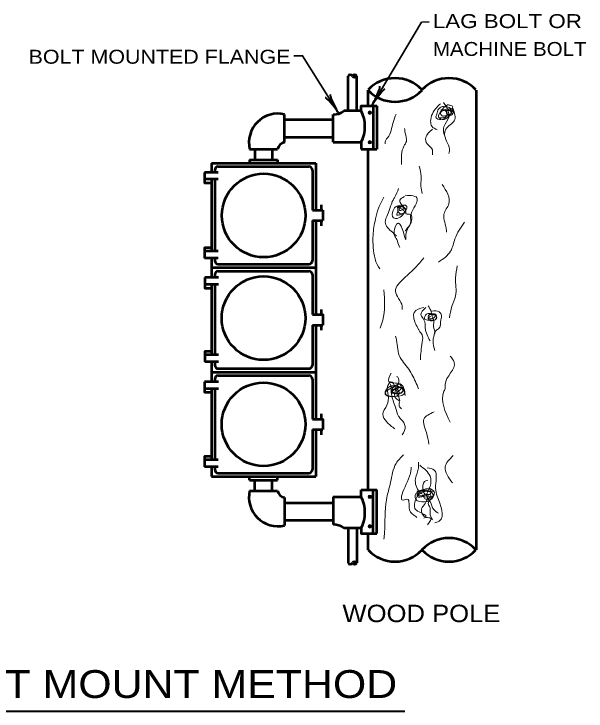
# Model space of a CAD drawing. Extents: x -286 to 394, y -156 to 284.
# Drawn here: x -179.2 to -97.1, y -8 to 92.1 of the extents above; entities that cross this region are included whole.
import ezdxf
from ezdxf.enums import TextEntityAlignment as Align

# ---------------------------------------------------------------- set-up
doc = ezdxf.new("R2010")
doc.units = 0
doc.header["$LTSCALE"] = 0.8
doc.layers.add('1', color=7, linetype='Continuous', lineweight=53)

msp = doc.modelspace()

# ---------------------------------------------------------------- hatches: boundary and pattern name
at = {"layer": '1'}
for points in [[(-127.854, 77.9357, 1), (-128.354, 77.9357, 1)], [(-127.854, 73.6894, 1), (-128.354, 73.6894, 1)], [(-127.854, 22.7843, 1), (-128.354, 22.7843, 1)], [(-127.854, 18.5379, 1), (-128.354, 18.5379, 1)]]:
    msp.add_hatch(color=256, dxfattribs=at).paths.add_polyline_path(points)

# ---------------------------------------------------------------- linework, layer by layer
at = {"layer": '1', "lineweight": 35}
for p, q in [((-127.7725, 79.0342), (-120.6713, 90.9517)), ((-120.6713, 90.9517), (-119.5732, 90.9644))]:
    msp.add_line(p, q, dxfattribs=at)
at = {"layer": '1'}
for p, q in [((-131.2278, 78.1877), (-131.2278, 83.1877)), ((-129.9778, 78.1877), (-129.9778, 83.1877)), ((-128.3528, 78.9377), (-128.3528, 81.1877)), ((-112.8528, 81.1877), (-112.8528, 15.1619)), ((-129.3528, 78.1877), (-131.8528, 78.1877)), ((-127.6028, 78.9377), (-127.6028, 72.6877)), ((-127.1028, 78.9377), (-127.1028, 72.6877)), ((-140.3528, 73.6877), (-140.3528, 77.6877)), ((-133.3528, 73.6877), (-133.3528, 77.6877)), ((-140.3528, 76.9377), (-133.3528, 76.9377)), ((-140.3528, 74.4377), (-133.3528, 74.4377)), ((-145.3528, 72.6877), (-141.3528, 72.6877)), ((-144.6028, 72.6877), (-144.6028, 71.1877)), ((-142.1028, 72.6877), (-142.1028, 71.1877)), ((-129.3528, 72.6877), (-127.1028, 72.6877)), ((-128.3528, 23.7859), (-128.3528, 72.6877)), ((-145.3528, 71.1877), (-141.3528, 71.1877)), ((-145.3528, 71.1877), (-145.3528, 70.6877)), ((-141.3528, 71.1877), (-141.3528, 70.6877)), ((-150.8528, 70.6877), (-135.8528, 70.6877)), ((-150.8528, 70.6877), (-150.8528, 69.3678)), ((-149.8528, 70.1877), (-136.8528, 70.1877)), ((-135.8528, 70.6877), (-135.8528, 63.9378)), ((-149.8528, 69.3678), (-151.8528, 69.3678)), ((-150.3528, 69.6877), (-150.3528, 69.3678)), ((-136.3528, 69.6877), (-136.3528, 63.9378)), ((-149.8528, 68.3678), (-151.8528, 68.3678)), ((-150.8528, 68.3678), (-150.8528, 58.0468)), ((-150.3528, 68.3678), (-150.3528, 58.0468)), ((-135.1028, 64.6877), (-135.1028, 63.9378)), ((-136.3528, 63.9378), (-134.8528, 63.9378)), ((-134.8528, 63.9378), (-134.8528, 62.4378)), ((-136.3528, 62.4378), (-136.3528, 56.6878)), ((-136.3528, 62.4378), (-134.8528, 62.4378)), ((-135.8528, 62.4378), (-135.8528, 48.9378)), ((-135.1028, 62.4378), (-135.1028, 61.6878)), ((-149.8528, 58.0468), (-151.8528, 58.0468)), ((-149.8528, 57.0468), (-151.8528, 57.0468)), ((-150.8528, 57.0468), (-150.8528, 54.2587)), ((-150.3528, 57.0468), (-150.3528, 56.6878)), ((-149.8528, 56.1878), (-136.8528, 56.1878)), ((-150.8528, 55.6878), (-135.8528, 55.6878)), ((-149.8528, 55.1878), (-136.8528, 55.1878)), ((-149.8113, 54.2587), (-151.8113, 54.2587)), ((-150.3528, 54.6878), (-150.3528, 54.2587)), ((-136.3528, 54.6878), (-136.3528, 48.9378)), ((-149.8113, 53.2587), (-151.8113, 53.2587)), ((-150.8528, 53.2587), (-150.8528, 43.1597)), ((-150.3528, 53.2587), (-150.3528, 43.1597)), ((-135.1028, 49.6878), (-135.1028, 48.9378)), ((-136.3528, 47.4378), (-134.8528, 47.4378)), ((-136.3528, 47.4378), (-136.3528, 41.6878)), ((-135.8528, 47.4378), (-135.8528, 33.9378)), ((-135.1028, 47.4378), (-135.1028, 46.6878)), ((-149.8113, 43.1597), (-151.8113, 43.1597)), ((-149.8113, 42.1597), (-151.8113, 42.1597)), ((-150.8528, 42.1597), (-150.8528, 39.2854)), ((-150.3528, 42.1597), (-150.3528, 41.6878)), ((-149.8528, 41.1878), (-136.8528, 41.1878)), ((-150.8528, 40.6878), (-135.8528, 40.6878)), ((-149.8528, 40.1878), (-136.8528, 40.1878)), ((-149.8279, 39.2854), (-151.8279, 39.2854)), ((-150.3528, 39.6878), (-150.3528, 39.2854)), ((-136.3528, 39.6878), (-136.3528, 33.9378)), ((-149.8279, 38.2854), (-151.8279, 38.2854)), ((-150.8528, 38.2854), (-150.8528, 28.0879)), ((-150.3528, 38.2854), (-150.3528, 28.0879)), ((-135.1028, 34.6878), (-135.1028, 33.9378)), ((-136.3528, 32.4378), (-134.8528, 32.4378)), ((-136.3528, 32.4378), (-136.3528, 26.6877)), ((-135.8528, 32.4378), (-135.8528, 25.6877)), ((-135.1028, 32.4378), (-135.1028, 31.6877)), ((-149.8543, 28.0879), (-151.8543, 28.0879)), ((-149.8543, 27.0879), (-151.8543, 27.0879)), ((-150.8528, 27.0879), (-150.8528, 25.6877)), ((-150.3528, 27.0879), (-150.3528, 26.6877)), ((-149.8528, 26.1877), (-136.8528, 26.1877)), ((-150.8528, 25.6877), (-135.8528, 25.6877)), ((-145.3528, 25.1619), (-145.3528, 25.6619)), ((-145.3528, 25.1619), (-141.3528, 25.1619)), ((-144.6028, 23.6619), (-144.6028, 25.1619)), ((-142.1028, 23.6619), (-142.1028, 25.1619)), ((-141.3528, 25.1619), (-141.3528, 25.6619)), ((-145.3528, 23.6619), (-141.3528, 23.6619)), ((-129.3528, 22.7859), (-129.3528, 23.7859)), ((-129.3528, 23.7859), (-127.1028, 23.7859)), ((-127.6028, 17.5359), (-127.6028, 23.7859)), ((-127.1028, 17.5359), (-127.1028, 23.7859)), ((-140.3528, 22.6619), (-140.3528, 18.6619)), ((-133.3528, 22.7859), (-129.3528, 22.7859)), ((-133.3528, 22.7859), (-133.3528, 18.7859)), ((-140.3528, 21.9119), (-133.3528, 21.9119)), ((-140.3528, 19.4119), (-133.3528, 19.4119)), ((-129.3528, 18.2859), (-131.8528, 18.2859)), ((-131.2278, 18.2859), (-131.2278, 13.2859)), ((-129.9778, 18.2859), (-129.9778, 13.2859)), ((-128.3528, 15.1619), (-128.3528, 17.5359))]:
    msp.add_line(p, q, dxfattribs=at)
at = {"layer": '1', "lineweight": 40}
msp.add_line((-195.529, -7.9817), (-123.0741, -7.9817), dxfattribs=at)
at = {"layer": '1', "lineweight": 35}
msp.add_lwpolyline([(-132.6176, 77.8785), (-137.7608, 86.1178), (-138.9907, 86.1178)], dxfattribs=at)
at = {"layer": '1'}
for points in [[(-129.3528, 78.1877), (-129.3528, 78.9377), (-127.1028, 78.9377)], [(-133.3528, 73.6877), (-129.3528, 73.6877), (-129.3528, 72.6877)], [(-151.8528, 69.3678), (-151.8528, 67.8678), (-150.8528, 67.8678)], [(-150.8528, 58.5468), (-151.8528, 58.5468), (-151.8528, 57.0468)], [(-151.8113, 54.2587), (-151.8113, 52.7587), (-150.8528, 52.7587)], [(-136.3528, 48.9378), (-134.8528, 48.9378), (-134.8528, 47.4378)], [(-150.8113, 43.6597), (-151.8113, 43.6597), (-151.8113, 42.1597)], [(-151.8279, 39.2854), (-151.8279, 37.7854), (-150.8279, 37.7854)], [(-136.3528, 33.9378), (-134.8528, 33.9378), (-134.8528, 32.4378)], [(-150.8543, 28.5879), (-151.8543, 28.5879), (-151.8543, 27.0879)], [(-129.3528, 18.2859), (-129.3528, 17.5359), (-127.1028, 17.5359)]]:
    msp.add_lwpolyline(points, dxfattribs=at)
at = {"layer": '1', "lineweight": 13}
for centre in [(-128.104, 77.9357), (-128.104, 73.6894), (-128.104, 22.7843), (-128.104, 18.5379)]:
    msp.add_circle(centre, 0.25, dxfattribs=at)
at = {"layer": '1'}
for centre in [(-143.3466, 63.1818), (-143.358, 48.4382), (-143.3584, 33.1901)]:
    msp.add_circle(centre, 6, dxfattribs=at)
for centre, radius, start, end in [((-130.9153, 82.9868), 0.3715, 32.74583, 147.25417), ((-130.2903, 82.9868), 0.3715, 32.74583, 147.25417), ((-130.2903, 83.3876), 0.3715, 212.74583, 327.25417), ((-124.4778, 77.5927), 5.2962, 42.97503, 137.02497), ((-116.7397, 77.5927), 5.2962, 42.97503, 137.02497), ((-124.4778, 84.7981), 5.2962, 222.97503, 317.02497), ((-133.2241, 79.8017), 2.1178, 266.51631, 310.35359), ((-133.5969, 75.9377), 4.8036, 332.0697, 27.9303), ((-141.2973, 73.6322), 4.164, 76.89015, 193.10985), ((-140.0693, 72.4042), 1.3145, 102.45679, 167.54321), ((-149.8528, 69.6877), 0.5, 90, 180), ((-136.8528, 69.6877), 0.5, 0, 90), ((-149.8528, 56.6878), 0.5, 180, 270), ((-136.8528, 56.6878), 0.5, 270, 0), ((-149.8528, 54.6878), 0.5, 90, 180), ((-136.8528, 54.6878), 0.5, 0, 90), ((-149.8528, 41.6878), 0.5, 180, 270), ((-136.8528, 41.6878), 0.5, 270, 0), ((-149.8528, 39.6878), 0.5, 90, 180), ((-136.8528, 39.6878), 0.5, 0, 90), ((-149.8528, 26.6877), 0.5, 180, 270), ((-136.8528, 26.6877), 0.5, 270, 0), ((-141.2973, 22.7174), 4.164, 166.89015, 283.10985), ((-140.0693, 23.9455), 1.3145, 192.45679, 257.54321), ((-133.5969, 20.5359), 4.8036, 332.0697, 27.9303), ((-133.2241, 16.672), 2.1178, 49.64641, 93.48369), ((-116.7397, 11.5669), 5.2962, 42.97503, 137.02497), ((-124.4778, 18.7723), 5.2962, 222.97503, 317.02497), ((-116.7397, 18.7723), 5.2962, 222.97503, 317.02497), ((-130.9153, 13.4869), 0.3715, 212.74583, 327.25417), ((-130.2903, 13.0861), 0.3715, 32.74583, 147.25417), ((-130.2903, 13.4869), 0.3715, 212.74583, 327.25417)]:
    msp.add_arc(centre, radius, start, end, dxfattribs=at)
at = {"layer": '1', "lineweight": 40}
for centre, major_axis, ratio, start_param, end_param in [((-127.4513, 80.113), (-0.7799, -1.6139), 0.122415, 0.89635335, 3.14159265), ((-127.0172, 79.8884), (1.05, 1.419), 0.07063, 6.28230741, 8.55970261), ((-133.4298, 78.6578), (1.078, -1.4321), 0.122415, 0.89635335, 3.14159265), ((-133.0314, 78.9411), (-0.7811, 1.583), 0.07063, 6.28230741, 8.55970261)]:
    msp.add_ellipse(centre, major_axis=major_axis, ratio=ratio, start_param=start_param, end_param=end_param, dxfattribs=at)
at = {"layer": '1', "lineweight": 13}
for points in [[(-117.9731, 79.2214), (-118.4955, 78.6988), (-119.3662, 76.6956), (-119.1921, 75.9988), (-118.4085, 75.4762)], [(-116.3187, 78.5247), (-117.1024, 78.0021), (-117.0153, 77.7407), (-116.58, 77.7407), (-115.9705, 78.0021), (-116.2317, 78.1762), (-116.58, 78.4375), (-117.5378, 78.2633), (-117.9731, 77.9149), (-117.7119, 77.4794), (-117.2765, 77.4794), (-116.6671, 77.4794), (-116.2317, 77.7407), (-116.1446, 78.0892), (-116.2317, 78.4375), (-116.2317, 78.873), (-116.4929, 78.9602), (-116.9282, 79.0472), (-117.1024, 78.9602), (-117.5378, 78.6118), (-117.9731, 77.9149), (-118.2343, 77.5666), (-118.1472, 77.2182), (-117.1895, 77.0439), (-116.6671, 77.4794), (-116.4058, 77.8278), (-116.4929, 78.1762), (-117.1895, 78.2633), (-117.3636, 78.3504), (-118.1472, 77.7407), (-118.2343, 77.3053), (-117.1024, 77.3923), (-116.3187, 78.0892), (-116.9282, 78.7859), (-117.2765, 78.7859), (-117.799, 78.7859), (-118.2343, 78.4375), (-118.4955, 77.7407), (-118.5826, 77.2182), (-117.886, 76.9568), (-117.1895, 77.3053), (-117.0153, 77.9149), (-117.4507, 78.3504), (-117.886, 78.4375)], [(-117.5378, 79.3957), (-117.1024, 78.7859), (-116.8412, 78.1762), (-116.7541, 77.3053), (-117.4507, 75.9117), (-117.5378, 75.4762), (-117.4507, 74.8665)], [(-116.1446, 78.5247), (-115.9705, 76.7827), (-117.1895, 75.5632), (-117.3636, 74.6923), (-116.6671, 72.4277), (-116.7541, 72.0793)], [(-124.3293, 77.7407), (-124.7647, 76.5213), (-125.5483, 74.3438), (-125.8095, 73.9955), (-125.8966, 73.4728)], [(-123.1103, 75.6503), (-123.0232, 75.0407), (-122.8491, 73.8212), (-123.1974, 73.1245), (-123.5457, 71.9051), (-123.5457, 71.0341), (-123.5457, 70.5115)], [(-119.105, 75.5632), (-120.0628, 74.3438), (-119.8887, 73.4728), (-119.105, 72.6018), (-119.105, 72.2535), (-119.105, 71.9051)], [(-121.0206, 70.2502), (-120.7594, 69.205), (-120.7594, 67.3759), (-120.5853, 66.3307)], [(-117.7119, 67.6372), (-116.7541, 64.85), (-117.4507, 63.3693), (-117.1024, 61.0177), (-117.1024, 60.7563)], [(-123.981, 67.0275), (-124.5034, 65.8081), (-124.7647, 65.3726), (-125.1129, 64.5016), (-125.5483, 63.2822), (-125.8966, 62.237), (-124.8517, 60.7563), (-124.2422, 60.2338)], [(-123.0232, 66.0694), (-121.2818, 65.5468), (-121.4559, 64.85), (-122.0654, 63.7177), (-122.2396, 63.108), (-122.2396, 62.0628), (-122.8491, 60.8434), (-122.9362, 59.7112), (-123.981, 62.0628), (-124.5905, 60.4079), (-124.2422, 59.7112), (-123.8939, 58.7531), (-123.8069, 58.5788)], [(-126.0707, 65.8081), (-126.8543, 64.2403), (-127.2897, 62.6725), (-127.638, 60.3208), (-127.638, 59.0143), (-126.8543, 55.7917), (-126.6803, 55.5303)], [(-123.1103, 65.8953), (-123.8069, 65.3726), (-122.9362, 63.6306), (-122.9362, 63.4564), (-122.4137, 63.3693), (-122.4137, 61.7144), (-122.762, 61.2789), (-123.0232, 60.9305)], [(-123.3715, 64.5016), (-123.8939, 64.0661), (-123.8069, 63.8919), (-123.4586, 63.979), (-123.2844, 64.2403), (-123.3715, 64.4145), (-123.8069, 64.4145), (-123.981, 64.4145), (-124.0681, 64.1532), (-123.8939, 63.5435), (-123.3715, 63.4564), (-122.9362, 64.0661), (-123.4586, 64.4145), (-123.981, 64.5016), (-124.0681, 64.4145), (-124.0681, 63.8048), (-124.2422, 63.2822), (-123.7198, 63.2822), (-123.1103, 63.6306), (-122.8491, 64.0661), (-122.762, 64.3274), (-123.1103, 64.6758), (-123.5457, 64.5888), (-123.8939, 64.5888), (-124.2422, 64.5016), (-124.7647, 63.8919), (-124.6776, 62.8468), (-124.1552, 62.7597), (-123.3715, 63.2822), (-123.1103, 63.7177), (-123.4586, 64.0661), (-123.8069, 64.2403), (-124.2422, 64.4145)], [(-114.4903, 62.237), (-115.8834, 59.7982), (-116.4929, 58.0562), (-118.2343, 56.4885)], [(-120.324, 57.0982), (-121.543, 55.7046), (-123.1974, 54.1367), (-124.4164, 52.3077), (-123.4586, 50.1302), (-123.4586, 49.6947)], [(-115.5351, 55.9658), (-115.7963, 54.2239), (-115.7963, 51.6109), (-116.3187, 50.1302), (-116.6671, 48.4753)], [(-126.0707, 52.4819), (-126.2448, 48.1269), (-126.5932, 46.9946)], [(-119.7145, 50.2173), (-119.2792, 49.3463), (-119.1921, 48.9108), (-118.9309, 48.0398), (-118.9309, 46.9946), (-118.7567, 46.3849), (-118.8438, 46.0365)], [(-120.324, 49.956), (-121.7172, 49.2592), (-121.8042, 48.5624), (-121.1077, 46.8204), (-121.0206, 46.6463), (-120.5853, 46.0365), (-120.5853, 44.9913), (-120.8465, 42.4654)], [(-120.0628, 49.956), (-120.7594, 48.9108), (-120.324, 48.214), (-120.1499, 46.9946), (-119.8887, 46.0365), (-119.4533, 45.1655)], [(-119.3662, 48.7366), (-119.7145, 48.3882), (-119.4533, 48.214), (-119.018, 48.1269), (-118.4955, 48.4753), (-118.8438, 48.9108), (-119.018, 48.9108), (-119.5404, 48.9108), (-119.7145, 48.6495), (-119.4533, 48.3882), (-118.9309, 48.4753), (-118.6697, 48.9108), (-119.3662, 49.085), (-119.9757, 48.9979), (-120.237, 48.3011), (-119.6275, 48.1269), (-119.3662, 48.0398), (-118.5826, 48.3882), (-118.6697, 48.9979), (-119.4533, 48.9979), (-119.5404, 48.9979), (-119.6275, 48.9979)], [(-119.1921, 49.4334), (-118.1472, 49.3463), (-117.799, 48.8237), (-117.886, 48.214), (-118.2343, 46.9075), (-118.4955, 46.7333), (-118.9309, 45.7752), (-119.018, 45.1655), (-118.7567, 43.7719)], [(-124.4164, 45.8623), (-124.1552, 44.6429), (-123.981, 43.3364), (-122.6749, 41.3332), (-121.543, 39.3298), (-121.1077, 38.2847)], [(-116.58, 42.988), (-115.9705, 42.1171), (-117.2765, 38.8943), (-117.2765, 38.4588), (-117.4507, 37.9363), (-116.58, 33.4942)], [(-125.0259, 40.5493), (-125.3742, 39.3298), (-123.7198, 38.9815), (-123.0232, 37.3266)], [(-124.2422, 40.1137), (-123.981, 39.7653), (-124.1552, 38.6331), (-124.3293, 36.8911), (-123.8939, 36.5427), (-123.8939, 35.8459), (-123.5457, 35.4104)], [(-123.8069, 36.6298), (-125.2871, 39.1557), (-125.5483, 38.6331), (-125.4612, 37.3266), (-125.6353, 35.933), (-126.2448, 34.6265), (-125.7224, 33.5813), (-124.5034, 32.5361)], [(-123.7198, 38.4588), (-124.8517, 37.8492), (-124.4164, 37.675), (-123.3715, 37.9363), (-123.2844, 38.2847), (-123.7198, 38.4588), (-124.3293, 38.3717), (-124.9388, 37.8492), (-124.4164, 37.675), (-123.8939, 38.0233), (-123.6328, 38.2847), (-123.7198, 38.8943), (-124.6776, 38.546), (-124.8517, 38.2847), (-124.9388, 37.7621), (-124.1552, 37.5878), (-123.4586, 37.7621), (-123.4586, 38.4588), (-123.8939, 38.546), (-124.0681, 38.6331), (-124.4164, 38.6331), (-125.8966, 37.5007), (-123.8939, 37.5878), (-123.8939, 37.8492), (-124.1552, 38.2847), (-124.1552, 38.6331), (-124.4164, 38.7202), (-125.4612, 38.4588), (-125.8966, 37.675), (-123.1103, 37.7621), (-123.5457, 38.3717), (-124.3293, 38.7202), (-125.1129, 38.6331)], [(-125.2, 38.9815), (-125.0259, 38.4588), (-125.0259, 38.1105), (-124.7647, 36.6298), (-124.4164, 35.6717), (-123.981, 34.3652), (-123.6328, 33.9297), (-123.0232, 32.8845), (-123.4586, 31.6651)], [(-118.8438, 34.9749), (-120.324, 33.9297), (-119.9757, 32.0135), (-119.6275, 30.3586)], [(-123.2844, 28.7908), (-124.3293, 27.5714), (-125.1129, 24.8713), (-125.7224, 22.3454), (-125.9837, 17.6421), (-126.0707, 16.684)], [(-116.1446, 28.7037), (-117.2765, 27.0488), (-116.2317, 24.7843)], [(-122.1525, 27.0488), (-122.1525, 26.7875), (-123.1103, 22.3454), (-122.762, 22.4326), (-122.3267, 20.6906), (-121.8913, 20.2551), (-121.3689, 19.8196)], [(-121.1077, 27.7457), (-121.1077, 26.9617), (-121.543, 25.3939), (-120.9335, 23.4778), (-120.5853, 23.2164)], [(-120.9335, 27.3102), (-119.4533, 25.7423), (-119.4533, 24.2617), (-119.8887, 22.7809), (-119.4533, 22.0842), (-118.9309, 20.9518), (-118.2343, 20.4292)], [(-119.8887, 26.9617), (-118.8438, 26.6133), (-118.6697, 24.0003), (-118.4085, 22.8681), (-118.1472, 19.297), (-118.4955, 19.1227), (-118.7567, 19.0357)], [(-119.8016, 25.1327), (-120.237, 24.9584), (-120.4982, 23.7391), (-120.4982, 23.6519), (-119.8887, 22.8681), (-120.4111, 21.4745), (-120.6723, 21.039), (-119.9757, 19.8196), (-119.3662, 19.7325), (-119.8016, 18.7744)], [(-119.8887, 23.2164), (-120.324, 22.9552), (-120.237, 22.5197), (-119.4533, 22.6938), (-119.3662, 23.0422), (-119.7145, 23.1293), (-120.0628, 23.1293), (-120.6723, 22.8681), (-120.4111, 22.7809), (-119.6275, 22.7809), (-118.9309, 22.9552), (-119.2792, 23.3907), (-119.8887, 23.5648), (-121.543, 23.1293), (-121.543, 22.5197), (-119.018, 22.7809), (-119.018, 23.1293), (-119.4533, 23.5648), (-120.4982, 23.7391), (-121.2818, 23.4778), (-121.2818, 23.1293), (-119.7145, 23.0422), (-119.6275, 23.0422), (-119.3662, 23.6519), (-120.4111, 23.8262), (-121.2818, 22.7809), (-120.324, 22.8681)], [(-119.6275, 24.0874), (-118.8438, 23.4778), (-119.6275, 22.0842), (-119.7145, 21.8228), (-119.4533, 21.2132), (-119.4533, 20.4292), (-119.105, 19.4712)], [(-118.9309, 23.5648), (-120.8465, 23.3036), (-121.543, 22.3454), (-121.6301, 21.1261), (-121.0206, 20.6035), (-120.0628, 19.9067), (-120.324, 19.7325)]]:
    msp.add_spline(points, degree=3, dxfattribs=at)

# ---------------------------------------------------------------- texts
at = {"layer": '1'}
for s, width, p in [('LAG BOLT OR', 1.2, (-119.0513, 90.0828)), ('MACHINE BOLT', 1.1, (-119.0513, 86.0828))]:
    msp.add_text(s, height=2, dxfattribs=dict(at, width=width)).set_placement(p)
for s, height, width, p in [('BOLT MOUNTED FLANGE', 2, 1.15, (-158.2965, 84.9686)), ('WOOD POLE', 2.5, 1.1, (-120.6911, 4.7863)), ('POST MOUNT METHOD', 4, 1.15, (-158.8555, -6.1044))]:
    msp.add_text(s, height=height, dxfattribs=dict(at, width=width)).set_placement(p, align=Align.CENTER)

doc.saveas('drawing.dxf')
